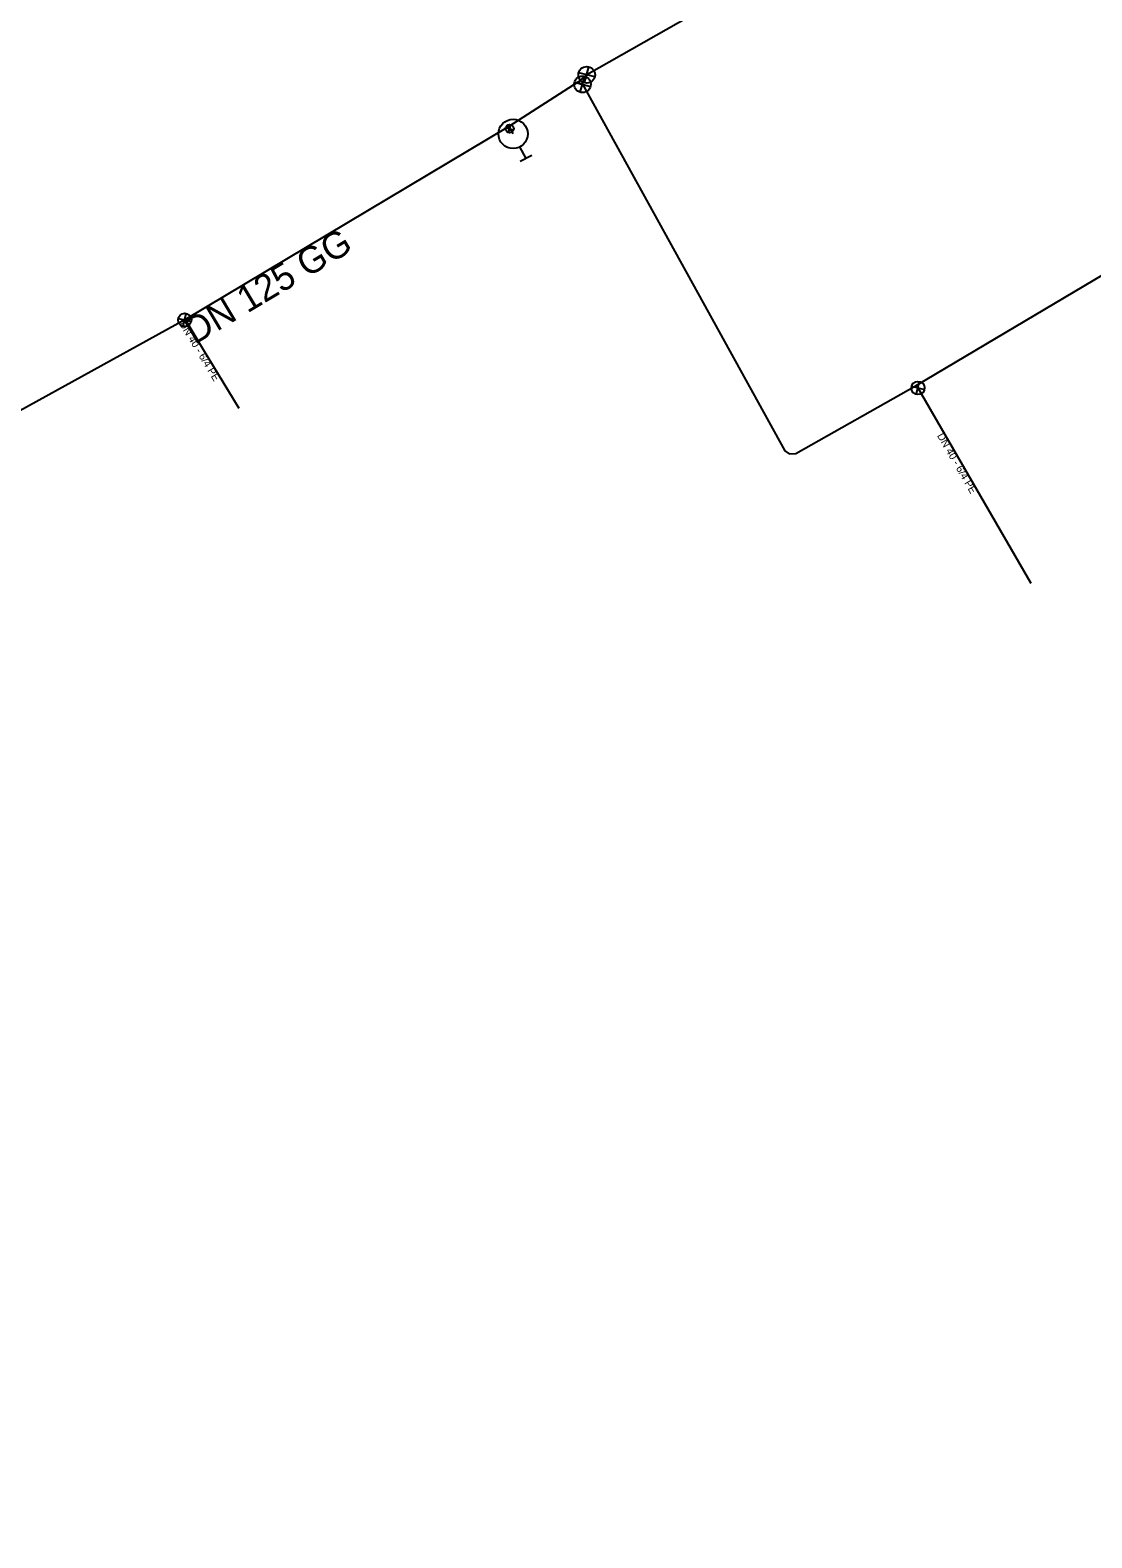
# Model space of a CAD drawing. Extents: x -443562 to -443270, y -1122830 to -1122511.
# Drawn here: x -443400.8 to -443336.9, y -1122829.6 to -1122738.8 of the extents above; entities that cross this region are included whole.
import ezdxf

# ---------------------------------------------------------------- set-up
doc = ezdxf.new("R2010")
doc.units = 0
for name, color, linetype in [('_hydrantova_odbocka_', 7, 'Continuous'), ('_pripojka_priblizne_', 7, 'Continuous'), ('_voda_smvak_prevzato_z_dokumentace_', 7, 'Continuous'), ('Default', 7, 'Continuous'), ('MoLevel 27', 7, 'Continuous'), ('MoLevel 28', 7, 'Continuous'), ('MoLevel 32', 7, 'Continuous'), ('MoLevel 46', 7, 'Continuous'), ('MoLevel 53', 7, 'Continuous')]:
    doc.layers.add(name, color=color, linetype=linetype)

# ---------------------------------------------------------------- blocks, each defined once
blk = doc.blocks.new('_uzaver_')
at = {"layer": 'Default'}
for p, q in [((-0.000035, -0.000035), (0.000035, 0.000035)), ((0.000035, -0.000035), (-0.000035, 0.000035))]:
    blk.add_line(p, q, dxfattribs=at)
for radius in [0.00005, 0.0000025]:
    blk.add_circle((0, 0), radius, dxfattribs=at)
blk = doc.blocks.new('_uzaver_pripojka_')
at = {"layer": 'Default'}
for p, q in [((-0.000035, -0.000035), (0.000035, 0.000035)), ((0.000035, -0.000035), (-0.000035, 0.000035))]:
    blk.add_line(p, q, dxfattribs=at)
for radius in [0.00005, 0.0000025]:
    blk.add_circle((0, 0), radius, dxfattribs=at)
blk = doc.blocks.new('_hydrant_voda_')
at = {"layer": 'Default'}
for p, q in [((-0.0000225, 0.000095), (0.0000225, 0.000095)), ((0, 0.000095), (0, 0.00005))]:
    blk.add_line(p, q, dxfattribs=at)
blk.add_circle((0, 0), 0.00005, dxfattribs=at)

msp = doc.modelspace()

# ---------------------------------------------------------------- linework, layer by layer
at = {"layer": '_hydrantova_odbocka_'}
msp.add_lwpolyline([(-443371.738, -1122745.057), (-443371.95, -1122744.74), (-443372, -1122744.61)], dxfattribs=at)
at = {"layer": '_pripojka_priblizne_'}
for points in [[(-443388.25, -1122761.6), (-443391.36, -1122756.47), (-443391.52, -1122756.26)], [(-443347.45, -1122760.22), (-443347.35, -1122760.36), (-443340.56, -1122772.12)]]:
    msp.add_lwpolyline(points, dxfattribs=at)
at = {"layer": '_voda_smvak_prevzato_z_dokumentace_'}
for p, q in [((-443367.303, -1122741.497), (-443367.834, -1122741.931)), ((-443367.834, -1122741.931), (-443372, -1122744.61)), ((-443367.834, -1122741.931), (-443367.56, -1122742.07))]:
    msp.add_line(p, q, dxfattribs=at)
for points in [[(-443346.631, -1122723.693), (-443343.999, -1122728.257), (-443367.303, -1122741.497)], [(-443367.56, -1122742.07), (-443355.37, -1122764.139), (-443355.102, -1122764.316), (-443354.703, -1122764.296), (-443347.45, -1122760.22), (-443331.96, -1122751.02), (-443321.2, -1122744.93), (-443320.285, -1122744.451), (-443320.06, -1122744.427), (-443319.914, -1122744.58), (-443317.228, -1122748.634), (-443313.793, -1122755.399), (-443299.23, -1122780.89), (-443296.72, -1122785.58), (-443283.95, -1122807.8), (-443282.35, -1122810.12), (-443274.899, -1122823.22), (-443271.477, -1122829.619)], [(-443372, -1122744.61), (-443391.52, -1122756.26), (-443405.96, -1122764.2), (-443431.37, -1122778.328)]]:
    msp.add_lwpolyline(points, dxfattribs=at)

# ---------------------------------------------------------------- block references
at = {"layer": 'MoLevel 27'}
for p, xscale, yscale, rotation in [((-443367.303, -1122741.497), 10000, 10000.000000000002, 29.856808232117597), ((-443367.56, -1122742.07), 9999.999999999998, 10000.000000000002, -60.703922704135), ((-443371.95, -1122744.74), 5000.000000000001, 5000, -60.30206388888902)]:
    msp.add_blockref('_uzaver_', p, dxfattribs=dict(at, xscale=xscale, yscale=yscale, rotation=rotation))
at = {"layer": 'MoLevel 28', "xscale": 17636.684303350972, "yscale": 17636.68430335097, "rotation": -152.10255555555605}
msp.add_blockref('_hydrant_voda_', (-443371.738, -1122745.057), dxfattribs=at)
at = {"layer": 'MoLevel 53'}
for p, xscale, yscale, rotation in [((-443391.52, -1122756.26), 7999.999999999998, 8000, -58.77417197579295), ((-443347.35, -1122760.36), 8000, 7999.999999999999, -59.761013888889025)]:
    msp.add_blockref('_uzaver_pripojka_', p, dxfattribs=dict(at, xscale=xscale, yscale=yscale, rotation=rotation))

# ---------------------------------------------------------------- texts
at = {"layer": 'MoLevel 32'}
for rotation, p in [(301.22583, (-443391.875, -1122756.499)), (300.00132, (-443346.217, -1122763.232))]:
    msp.add_text('DN 40 - 6/4 PE', height=0.455, rotation=rotation, dxfattribs=at).set_placement(p)
at = {"layer": 'MoLevel 46'}
msp.add_text('DN 125 GG', height=1.6049, rotation=30.82976, dxfattribs=at).set_placement((-443390.925, -1122757.774))

doc.saveas('drawing.dxf')
